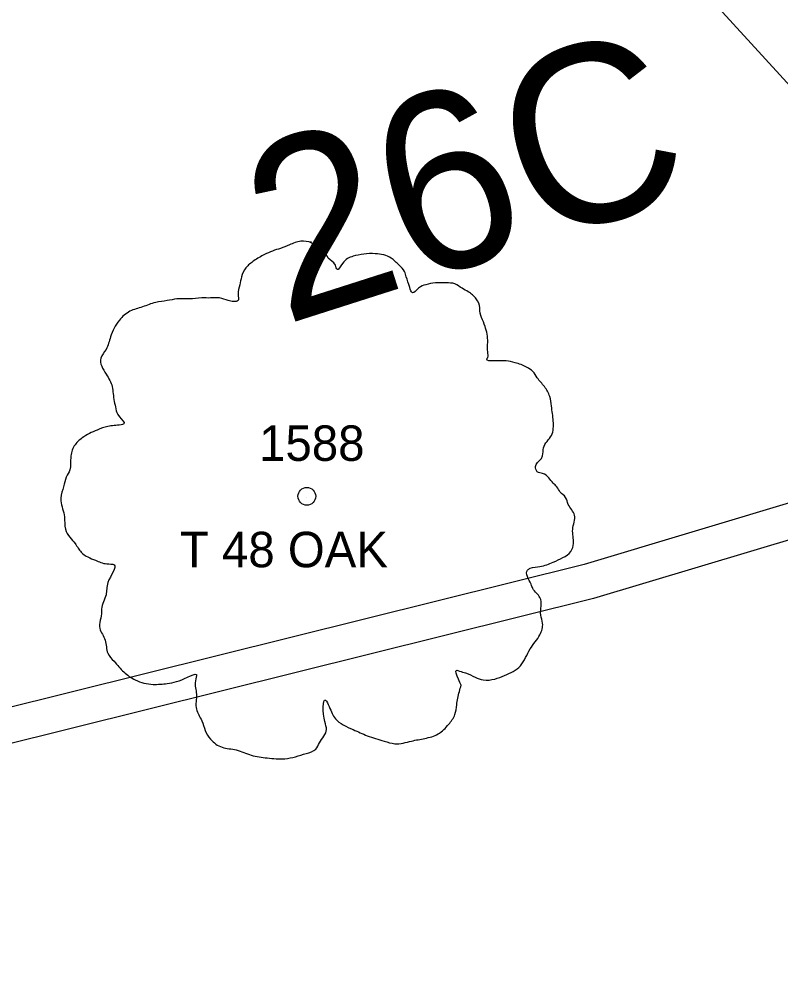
# Model space of a CAD drawing. Extents: x 1964982 to 1970452, y 1116335 to 1119906.
# Drawn here: x 1966698.37 to 1966719.86, y 1117449.81 to 1117477 of the extents above; entities that cross this region are included whole.
import ezdxf

# ---------------------------------------------------------------- set-up
doc = ezdxf.new("R2010")
doc.units = 0
for name, color, linetype in [('RD_EX_Driveway', 7, 'Continuous'), ('RD_EX_VEG', 7, 'Continuous'), ('RD_EX_VEG_txCode', 7, 'Continuous'), ('RD_HC_CL_Rel', 7, 'Continuous'), ('RD_PD_CstnLmt', 7, 'Continuous'), ('RD_PD_Final_TrvlWay', 7, 'Continuous'), ('RD_PD_RW', 7, 'Continuous'), ('RD_PD_TX_CstnLmt', 7, 'Continuous')]:
    doc.layers.add(name, color=color, linetype=linetype)

msp = doc.modelspace()

# ---------------------------------------------------------------- linework, layer by layer
at = {"layer": 'RD_EX_Driveway'}
msp.add_lwpolyline([(1966589.3, 1117436.331), (1966587.977, 1117456.65), (1966594.083, 1117483.042), (1966609.697, 1117504.074), (1966638.325, 1117518.314), (1966661.317, 1117517.134), (1966685.434, 1117507.038), (1966705.558, 1117491.043), (1966722.871, 1117472.119), (1966734.107, 1117458.19)], dxfattribs=at)
at = {"layer": 'RD_EX_VEG'}
for centre, radius in [((1966706.486, 1117463.552), 0.25), ((1966706.486, 1117463.552), 0.25), ((1966706.473, 1117463.533), 0.0001), ((1966706.473, 1117463.533), 0.0001)]:
    msp.add_circle(centre, radius, dxfattribs=at)
for points in [[(1966706.618, 1117470.719), (1966706.318, 1117470.744), (1966705.993, 1117470.644), (1966705.743, 1117470.545), (1966705.518, 1117470.47), (1966705.293, 1117470.37), (1966704.993, 1117470.195), (1966704.768, 1117469.995), (1966704.643, 1117469.745), (1966704.593, 1117469.52), (1966704.544, 1117469.245), (1966704.544, 1117469.07), (1966704.419, 1117469.045), (1966704.269, 1117469.07), (1966704.019, 1117469.145), (1966703.769, 1117469.145), (1966703.519, 1117469.145), (1966703.169, 1117469.12), (1966702.819, 1117469.12), (1966702.544, 1117469.07), (1966702.22, 1117469.02), (1966701.845, 1117468.895), (1966701.495, 1117468.77), (1966701.195, 1117468.52), (1966700.945, 1117468.046), (1966700.82, 1117467.696), (1966700.67, 1117467.446), (1966700.82, 1117466.996), (1966700.995, 1117466.646), (1966701.02, 1117466.446), (1966701.095, 1117466.022), (1966701.195, 1117465.797), (1966701.32, 1117465.597), (1966701.245, 1117465.572), (1966700.87, 1117465.522), (1966700.57, 1117465.422), (1966700.145, 1117465.197), (1966699.921, 1117464.972), (1966699.821, 1117464.647), (1966699.796, 1117464.297), (1966699.696, 1117464.097), (1966699.621, 1117463.822), (1966699.596, 1117463.747), (1966699.546, 1117463.423), (1966699.646, 1117462.973), (1966699.671, 1117462.623), (1966699.796, 1117462.398), (1966699.946, 1117462.223), (1966700.12, 1117461.973), (1966700.52, 1117461.748), (1966700.845, 1117461.648), (1966701.045, 1117461.623), (1966700.87, 1117461.124), (1966700.82, 1117460.774), (1966700.695, 1117460.374), (1966700.695, 1117460.299), (1966700.645, 1117459.824), (1966700.795, 1117459.499), (1966700.87, 1117459.125), (1966701.045, 1117458.9), (1966701.32, 1117458.6), (1966701.645, 1117458.375), (1966702.145, 1117458.25), (1966702.544, 1117458.275), (1966703.119, 1117458.45), (1966703.369, 1117458.525), (1966703.344, 1117458.35), (1966703.369, 1117457.975), (1966703.369, 1117457.55), (1966703.519, 1117457.225), (1966703.619, 1117456.95), (1966703.769, 1117456.701), (1966704.094, 1117456.476), (1966704.494, 1117456.401), (1966704.918, 1117456.251), (1966705.368, 1117456.176), (1966705.868, 1117456.151), (1966706.468, 1117456.301), (1966706.743, 1117456.426), (1966706.843, 1117456.601), (1966707.042, 1117456.975), (1966706.992, 1117457.2), (1966707.017, 1117457.8), (1966707.117, 1117457.625), (1966707.292, 1117457.275), (1966707.792, 1117456.975), (1966708.192, 1117456.801), (1966708.667, 1117456.651), (1966708.967, 1117456.576), (1966709.441, 1117456.651), (1966709.816, 1117456.726), (1966710.191, 1117456.851), (1966710.491, 1117457.125), (1966710.666, 1117457.4), (1966710.716, 1117457.675), (1966710.791, 1117458.05), (1966710.841, 1117458.225)], [(1966706.618, 1117470.719), (1966706.318, 1117470.744), (1966705.993, 1117470.644), (1966705.743, 1117470.545), (1966705.518, 1117470.47), (1966705.293, 1117470.37), (1966704.993, 1117470.195), (1966704.768, 1117469.995), (1966704.643, 1117469.745), (1966704.593, 1117469.52), (1966704.544, 1117469.245), (1966704.544, 1117469.07), (1966704.419, 1117469.045), (1966704.269, 1117469.07), (1966704.019, 1117469.145), (1966703.769, 1117469.145), (1966703.519, 1117469.145), (1966703.169, 1117469.12), (1966702.819, 1117469.12), (1966702.544, 1117469.07), (1966702.22, 1117469.02), (1966701.845, 1117468.895), (1966701.495, 1117468.77), (1966701.195, 1117468.52), (1966700.945, 1117468.046), (1966700.82, 1117467.696), (1966700.67, 1117467.446), (1966700.82, 1117466.996), (1966700.995, 1117466.646), (1966701.02, 1117466.446), (1966701.095, 1117466.022), (1966701.195, 1117465.797), (1966701.32, 1117465.597), (1966701.245, 1117465.572), (1966700.87, 1117465.522), (1966700.57, 1117465.422), (1966700.145, 1117465.197), (1966699.921, 1117464.972), (1966699.821, 1117464.647), (1966699.796, 1117464.297), (1966699.696, 1117464.097), (1966699.621, 1117463.822), (1966699.596, 1117463.747), (1966699.546, 1117463.423), (1966699.646, 1117462.973), (1966699.671, 1117462.623), (1966699.796, 1117462.398), (1966699.946, 1117462.223), (1966700.12, 1117461.973), (1966700.52, 1117461.748), (1966700.845, 1117461.648), (1966701.045, 1117461.623), (1966700.87, 1117461.124), (1966700.82, 1117460.774), (1966700.695, 1117460.374), (1966700.695, 1117460.299), (1966700.645, 1117459.824), (1966700.795, 1117459.499), (1966700.87, 1117459.125), (1966701.045, 1117458.9), (1966701.32, 1117458.6), (1966701.645, 1117458.375), (1966702.145, 1117458.25), (1966702.544, 1117458.275), (1966703.119, 1117458.45), (1966703.369, 1117458.525), (1966703.344, 1117458.35), (1966703.369, 1117457.975), (1966703.369, 1117457.55), (1966703.519, 1117457.225), (1966703.619, 1117456.95), (1966703.769, 1117456.701), (1966704.094, 1117456.476), (1966704.494, 1117456.401), (1966704.918, 1117456.251), (1966705.368, 1117456.176), (1966705.868, 1117456.151), (1966706.468, 1117456.301), (1966706.743, 1117456.426), (1966706.843, 1117456.601), (1966707.042, 1117456.975), (1966706.992, 1117457.2), (1966707.017, 1117457.8), (1966707.117, 1117457.625), (1966707.292, 1117457.275), (1966707.792, 1117456.975), (1966708.192, 1117456.801), (1966708.667, 1117456.651), (1966708.967, 1117456.576), (1966709.441, 1117456.651), (1966709.816, 1117456.726), (1966710.191, 1117456.851), (1966710.491, 1117457.125), (1966710.666, 1117457.4), (1966710.716, 1117457.675), (1966710.791, 1117458.05), (1966710.841, 1117458.225)], [(1966710.841, 1117458.225), (1966710.766, 1117458.4), (1966710.716, 1117458.65), (1966710.791, 1117458.625), (1966710.966, 1117458.575), (1966711.241, 1117458.45), (1966711.466, 1117458.375), (1966711.79, 1117458.4), (1966712.065, 1117458.5), (1966712.515, 1117458.775), (1966712.79, 1117459.249), (1966713.065, 1117459.649), (1966713.14, 1117459.974), (1966713.09, 1117460.199), (1966713.065, 1117460.699), (1966712.865, 1117460.949), (1966712.815, 1117461.074), (1966712.715, 1117461.473), (1966712.79, 1117461.523), (1966713.065, 1117461.573), (1966713.44, 1117461.698), (1966713.715, 1117461.823), (1966713.939, 1117461.998), (1966714.014, 1117462.223), (1966713.989, 1117462.623), (1966714.039, 1117463.023), (1966713.964, 1117463.173), (1966713.864, 1117463.323), (1966713.789, 1117463.523), (1966713.64, 1117463.672), (1966713.54, 1117463.822), (1966713.44, 1117463.922), (1966713.315, 1117464.072), (1966713.14, 1117464.197), (1966712.99, 1117464.247), (1966712.94, 1117464.397), (1966713.09, 1117464.597), (1966713.14, 1117464.697), (1966713.165, 1117464.922), (1966713.39, 1117465.272), (1966713.44, 1117465.672), (1966713.39, 1117466.096), (1966713.34, 1117466.371), (1966713.19, 1117466.646), (1966712.99, 1117466.896), (1966712.865, 1117467.071), (1966712.69, 1117467.196), (1966712.365, 1117467.321), (1966712.115, 1117467.371), (1966711.765, 1117467.371), (1966711.565, 1117467.421), (1966711.59, 1117467.471), (1966711.59, 1117467.621), (1966711.59, 1117467.896), (1966711.515, 1117468.345), (1966711.366, 1117468.845), (1966711.366, 1117468.87), (1966711.266, 1117469.12), (1966711.041, 1117469.32), (1966710.866, 1117469.42), (1966710.666, 1117469.545), (1966710.416, 1117469.57), (1966710.116, 1117469.57), (1966709.841, 1117469.52), (1966709.641, 1117469.42), (1966709.466, 1117469.295), (1966709.391, 1117469.445), (1966709.291, 1117469.745), (1966709.241, 1117469.895), (1966709.092, 1117470.07), (1966708.867, 1117470.27), (1966708.417, 1117470.395), (1966707.792, 1117470.32), (1966707.492, 1117470.12), (1966707.342, 1117469.945), (1966707.292, 1117470.07), (1966707.092, 1117470.27), (1966706.992, 1117470.445), (1966706.818, 1117470.57), (1966706.668, 1117470.669), (1966706.568, 1117470.719)], [(1966710.841, 1117458.225), (1966710.766, 1117458.4), (1966710.716, 1117458.65), (1966710.791, 1117458.625), (1966710.966, 1117458.575), (1966711.241, 1117458.45), (1966711.466, 1117458.375), (1966711.79, 1117458.4), (1966712.065, 1117458.5), (1966712.515, 1117458.775), (1966712.79, 1117459.249), (1966713.065, 1117459.649), (1966713.14, 1117459.974), (1966713.09, 1117460.199), (1966713.065, 1117460.699), (1966712.865, 1117460.949), (1966712.815, 1117461.074), (1966712.715, 1117461.473), (1966712.79, 1117461.523), (1966713.065, 1117461.573), (1966713.44, 1117461.698), (1966713.715, 1117461.823), (1966713.939, 1117461.998), (1966714.014, 1117462.223), (1966713.989, 1117462.623), (1966714.039, 1117463.023), (1966713.964, 1117463.173), (1966713.864, 1117463.323), (1966713.789, 1117463.523), (1966713.64, 1117463.672), (1966713.54, 1117463.822), (1966713.44, 1117463.922), (1966713.315, 1117464.072), (1966713.14, 1117464.197), (1966712.99, 1117464.247), (1966712.94, 1117464.397), (1966713.09, 1117464.597), (1966713.14, 1117464.697), (1966713.165, 1117464.922), (1966713.39, 1117465.272), (1966713.44, 1117465.672), (1966713.39, 1117466.096), (1966713.34, 1117466.371), (1966713.19, 1117466.646), (1966712.99, 1117466.896), (1966712.865, 1117467.071), (1966712.69, 1117467.196), (1966712.365, 1117467.321), (1966712.115, 1117467.371), (1966711.765, 1117467.371), (1966711.565, 1117467.421), (1966711.59, 1117467.471), (1966711.59, 1117467.621), (1966711.59, 1117467.896), (1966711.515, 1117468.345), (1966711.366, 1117468.845), (1966711.366, 1117468.87), (1966711.266, 1117469.12), (1966711.041, 1117469.32), (1966710.866, 1117469.42), (1966710.666, 1117469.545), (1966710.416, 1117469.57), (1966710.116, 1117469.57), (1966709.841, 1117469.52), (1966709.641, 1117469.42), (1966709.466, 1117469.295), (1966709.391, 1117469.445), (1966709.291, 1117469.745), (1966709.241, 1117469.895), (1966709.092, 1117470.07), (1966708.867, 1117470.27), (1966708.417, 1117470.395), (1966707.792, 1117470.32), (1966707.492, 1117470.12), (1966707.342, 1117469.945), (1966707.292, 1117470.07), (1966707.092, 1117470.27), (1966706.992, 1117470.445), (1966706.818, 1117470.57), (1966706.668, 1117470.669), (1966706.568, 1117470.719)]]:
    msp.add_spline(points, degree=3, dxfattribs=at)
at = {"layer": 'RD_HC_CL_Rel'}
msp.add_arc((1966373.74, 1118527.456), 1145.915, 281.904723, 295.046328, dxfattribs=at)
at = {"layer": 'RD_PD_CstnLmt'}
for p, q in [((1966761.449, 1117474.738), (1966714.573, 1117460.668)), ((1966714.573, 1117460.668), (1966667.156, 1117448.875))]:
    msp.add_line(p, q, dxfattribs=at)
at = {"layer": 'RD_PD_Final_TrvlWay'}
for radius in [1134.915, 1156.915]:
    msp.add_arc((1966373.74, 1118527.456), radius, 281.904723, 295.046328, dxfattribs=at)
at = {"layer": 'RD_PD_RW'}
for p, q in [((1966760.987, 1117475.643), (1966714.309, 1117461.633)), ((1966714.309, 1117461.633), (1966666.917, 1117449.846))]:
    msp.add_line(p, q, dxfattribs=at)

# ---------------------------------------------------------------- texts
at = {"layer": 'RD_EX_VEG_txCode'}
for s, p in [('1588', (1966705.139, 1117464.552)), ('1588', (1966705.139, 1117464.552)), ('T 48 OAK', (1966702.903, 1117461.552)), ('T 48 OAK', (1966702.903, 1117461.552))]:
    msp.add_text(s, height=1, dxfattribs=at).set_placement(p)
at = {"layer": 'RD_PD_TX_CstnLmt'}
msp.add_text('26C', height=5, rotation=17.7184, dxfattribs=at).set_placement((1966705.844, 1117468.377))

doc.saveas('drawing.dxf')
